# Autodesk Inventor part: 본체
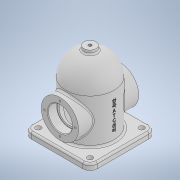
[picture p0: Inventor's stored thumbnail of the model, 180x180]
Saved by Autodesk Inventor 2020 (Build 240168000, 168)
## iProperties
Created: 2021-07
Part Number: 본체
Material: 일반
Document SubType Name: Modeling
Designer: Owner
Density: 1 g/cm^3
Appearance: 기본값
Author: Owner
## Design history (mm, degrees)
sketch "스케치1"
  geometry: C1 r 40 at (0, 0); 1 further point
  constraints: 1 centre point, 1 coincident
  dimensions: "d0" = 80 diameter of C1
extrude "돌출1" new body sketch "스케치1" distance "d1" = 124; taper "d2" = 0 deg
fillet "모깎기1" dims "d3" = 40
feature "쉘1" dims "d4" = 8
sketch "스케치2"
  geometry: L1 (55, 55)-(-55, 55); L2 (-55, 55)-(-55, -55); L3 (-55, -55)-(55, -55); L4 (55, -55)-(55, 55); L5 (55, 55)-(-55, -55); L6 (-55, 55)-(55, -55); C1 r 32 at (0, 0) reference; C2 r 40 at (0, 0) reference; 1 further point
  constraints: 12 end point, 2 midpoint, 2 parallel, 1 horizontal, 1 perpendicular
  dimensions: "d5" = 110 distance of L3.end L2.end; "d6" = 110 distance of L2.end L1.end
extrude "돌출2" join sketch "스케치2" distance "d7" = 10; taper "d8" = 0 deg
node "작업 평면1"
sketch "스케치3"
  geometry: L1 (-55, 0)-(55, 0) reference; C1 r 31 at (0, 48); 2 further points
  constraints: 1 centre point, 1 midpoint, 1 vertical alignment
  dimensions: "d10" = 62 diameter of C1; "d11" = 48 distance from line of L1 C1.centre
extrude "돌출3" join sketch "스케치3" stored distance "d12" = 10; taper "d13" = 0 deg
sketch "스케치4"
  geometry: C1 r 31 at (0, 0) reference; 2 further points
  constraints: 1 coincident
hole "구멍1" sketch "스케치4" at (0, 0) diameter "d14" = 33; stored, may be unused: countersink angle "d18" = 90 deg, drill point angle "d20" = 118 deg; dims "d15" = 6, "d16" = 40, "d17" = 15, "d19" = 8
sketch "스케치5"
  geometry: C1 r 20 at (0, 0) reference; 2 further points
  constraints: 1 vertical alignment
  dimensions: "d21" = 25.5 distance of C1.centre point (0, 25.5)
hole "구멍2" sketch "스케치5" at (0, 25.5) diameter "d22" = 3.242; stored, may be unused: countersink angle "d26" = 90 deg, drill point angle "d28" = 118 deg; dims "d23" = 8, "d24" = 40, "d25" = 15, "d27" = 10
node "작업 평면2"
sketch "스케치6"
  geometry: C1 r 10 at (0, 0); 1 further point
  constraints: 1 centre point, 1 coincident
  dimensions: "d33" = 20 diameter of C1
extrude "돌출4" join sketch "스케치6" stored distance "d34" = 124; taper "d35" = 0 deg
sketch "스케치8"
  geometry: C1 r 10 at (0, 0) reference; 2 further points
  constraints: 1 coincident
hole "구멍3" sketch "스케치8" at (0, 0) diameter "d36" = 5.1881; stored, may be unused: countersink angle "d40" = 90 deg, drill point angle "d42" = 118 deg; dims "d37" = 30, "d38" = 40, "d39" = 15, "d41" = 16
fillet "모깎기2" dims "d43" = 12
fillet "모깎기3" dims "d44" = 3
sketch "스케치9"
  geometry: A1 r 12 centre (43, -43) between (43, -55) and (55, -43) reference; 2 further points
  constraints: 1 coincident
hole "구멍4" sketch "스케치9" at (43, -43) diameter "d45" = 9; stored, may be unused: countersink angle "d49" = 90 deg, drill point angle "d51" = 118 deg; dims "d46" = 30, "d47" = 40, "d48" = 15, "d50" = 16
fillet "모깎기4" dims "d55" = 0.3
node "작업 평면3"
sketch "스케치10"
  geometry: L1 (0, 43)-(0, -43) reference; 3 further points
  constraints: 1 horizontal alignment, 1 midpoint, 1 other
  dimensions: "d56" = 48 distance from line of L1 point (48, 0)
feature "엠보싱1" sketch "스케치10" dims "d1" = 124, "d2" = 0, "d57" = 0.5, "d58" = 0
chamfer "모따기1" distance "d59" = 1; stored, may be unused: second distance "d60" = 2, angle "d61" = 45 deg
node "솔리드1"
pattern_circular "원형 패턴1" dims angle "d30" = 360 deg
mirror "미러1"
pattern_circular "원형 패턴2" dims angle "d53" = 360 deg
node "절단 모서리 투영1"
feature "A9D066F2-1C7D-4E18-AEED-F7BC21143FA4" dims "d36" = 5.1881, "d37" = 30, "d38" = 40, "d39" = 15, "d40" = 90 deg, "d41" = 16, "d42" = 118 deg
other parameters: "d32" = 129
